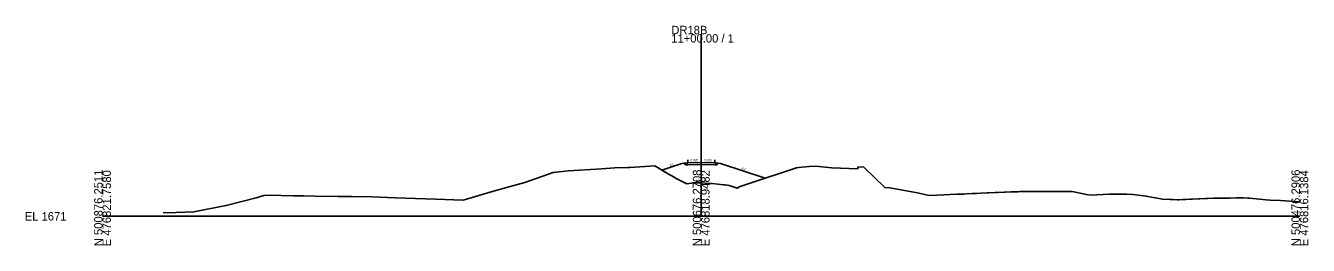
# Model space of a CAD drawing. Extents: x -26 to 403, y -10 to 2578.
# Drawn here: x -25.7 to 402.8, y 490.3 to 563.7 of the extents above; entities that cross this region are included whole.
import ezdxf

# ---------------------------------------------------------------- set-up
doc = ezdxf.new("R2010")
doc.units = 0
for name, color, linetype in [('Exist Cross Section Cell', 7, 'Continuous'), ('Exist XS Center Line Elevation Label', 7, 'Continuous'), ('Exist XS Ground Line', 7, 'Continuous'), ('Prop XS Earthwork Shape', 7, 'Continuous'), ('Prop XS EOT Tick Mark', 7, 'Continuous'), ('Prop XS Finish Grade', 7, 'Continuous'), ('Prop XS Finish Grade Earthwork', 7, 'Continuous'), ('Prop XS Finish Grade Pavement', 7, 'Continuous'), ('Prop XS Pvmt Edge Slope', 7, 'Continuous'), ('Prop XS SE Text', 7, 'Continuous'), ('Prop XS Shoulder Borrow Shape', 7, 'Continuous'), ('Prop XS Side Slope Text', 7, 'Continuous'), ('Prop XS Subgrade Earthwork', 7, 'Continuous')]:
    doc.layers.add(name, color=color, linetype=linetype)

msp = doc.modelspace()

# ---------------------------------------------------------------- linework, layer by layer
at = {"layer": 'Exist Cross Section Cell'}
for p, q in [((200, 500), (200, 560.82)), ((0, 500), (200, 500)), ((200, 500), (400, 500))]:
    msp.add_line(p, q, dxfattribs=at)
at = {"layer": 'Exist XS Ground Line'}
msp.add_lwpolyline([(20.23, 501.28), (21.67, 501.18), (30.44, 501.46), (40.61, 503.46), (41.28, 503.61), (51.27, 506.16), (53.84, 506.98), (56.42, 507.09), (59.68, 506.95), (63.72, 506.89), (67.17, 506.79), (70.98, 506.71), (78.74, 506.64), (83.24, 506.63), (89.91, 506.53), (97.84, 506.18), (107.88, 505.84), (111.23, 505.68), (120.53, 505.36), (129.88, 508.19), (136.21, 509.9), (141.11, 511.31), (150.55, 514.65), (155.67, 515.17), (166.64, 515.9), (171.16, 516.21), (175.45, 516.31), (176.16, 516.35), (184.48, 516.82), (189.01, 514.17), (189.57, 513.85), (190.15, 513.51), (191.86, 512.51), (195.19, 510.84), (196.61, 511.07), (197.17, 511.21), (197.91, 511.22), (198.83, 511.21), (199.16, 511.23), (200, 511.17), (202.69, 510.95), (203.61, 510.97), (207.44, 510.49), (208.06, 510.48), (209.3, 510.25), (210.03, 510.11), (212.01, 509.39), (213.05, 509.91), (215.39, 510.69), (231.82, 516.24), (232.6, 516.31), (233.65, 516.4), (234.93, 516.51), (236.04, 516.61), (238.17, 516.79), (243.69, 516.22), (252.36, 515.87), (252.37, 516.51), (254.34, 516.38), (261.31, 509.62), (263.07, 509.48), (272.24, 507.86), (276.04, 506.99), (278.86, 507.09), (285.42, 507.4), (285.86, 507.4), (287.1, 507.36), (287.73, 507.44), (288.64, 507.49), (290.37, 507.58), (291.14, 507.62), (292.02, 507.67), (293.58, 507.73), (295.52, 507.81), (296.1, 507.83), (298.16, 507.92), (298.63, 507.94), (299.11, 507.96), (301.17, 508.03), (301.63, 508.05), (303.59, 508.13), (305.78, 508.22), (306.42, 508.25), (307.21, 508.26), (308.63, 508.29), (311.05, 508.29), (313.85, 508.28), (316.37, 508.26), (318.83, 508.25), (320.7, 508.25), (321.08, 508.25), (322.68, 508.25), (323.28, 508.25), (323.93, 508.23), (328.71, 507.27), (330.22, 507.04), (336.32, 507.44), (339.05, 507.4), (342.13, 507.4), (344.24, 507.32), (345.32, 507.16), (346.82, 507), (348.71, 506.73), (350.99, 506.32), (351.82, 506.18), (354.09, 505.72), (356.65, 505.65), (357.56, 505.6), (359.11, 505.49), (359.69, 505.52), (360.9, 505.57), (361.87, 505.62), (363.25, 505.69), (363.64, 505.71), (364.09, 505.73), (366.14, 505.82), (366.62, 505.84), (368.64, 505.91), (369.15, 505.94), (371.13, 506.03), (371.9, 506.07), (372.34, 506.07), (373.62, 506.07), (375.5, 506.1), (376.11, 506.11), (376.73, 506.11), (378.6, 506.13), (379.58, 506.13), (381.17, 506.14), (382.65, 506.11), (383.22, 506.06), (388.77, 505.5), (390.1, 505.38), (393.57, 505.27), (399.61, 504.89), (400, 504.77)], dxfattribs=at)
at = {"layer": 'Prop XS Earthwork Shape'}
msp.add_lwpolyline([(206.5, 517.67), (221.38, 512.71), (215.39, 510.69), (213.05, 509.91), (212.01, 509.39), (210.03, 510.11), (209.3, 510.25), (208.06, 510.48), (207.44, 510.49), (203.61, 510.97), (202.69, 510.95), (200, 511.17), (199.16, 511.23), (198.83, 511.21), (197.91, 511.22), (197.17, 511.21), (196.61, 511.07), (195.19, 510.84), (191.86, 512.51), (190.15, 513.51), (189.57, 513.85), (189.01, 514.17), (186.83, 515.45), (193.5, 517.67), (194.24, 517.73), (194.82, 517.15), (195.5, 517.16), (200, 517.25), (204.5, 517.16), (205.18, 517.15), (205.76, 517.73)], close=True, dxfattribs=at)
at = {"layer": 'Prop XS EOT Tick Mark'}
for p, q in [((195.5, 517.83), (195.5, 518.83)), ((204.5, 517.83), (204.5, 518.83))]:
    msp.add_line(p, q, dxfattribs=at)
at = {"layer": 'Prop XS Finish Grade'}
for p, q in [((195.5, 517.83), (194.24, 517.73)), ((204.5, 517.83), (205.76, 517.73))]:
    msp.add_line(p, q, dxfattribs=at)
at = {"layer": 'Prop XS Finish Grade Earthwork'}
for p, q in [((193.5, 517.67), (186.83, 515.45)), ((194.24, 517.73), (193.5, 517.67)), ((205.76, 517.73), (206.5, 517.67)), ((206.5, 517.67), (221.38, 512.71))]:
    msp.add_line(p, q, dxfattribs=at)
at = {"layer": 'Prop XS Finish Grade Pavement'}
for p, q in [((195.5, 517.83), (200, 517.92)), ((200, 517.92), (204.5, 517.83))]:
    msp.add_line(p, q, dxfattribs=at)
at = {"layer": 'Prop XS Pvmt Edge Slope'}
for p, q in [((195.5, 517.83), (194.82, 517.15)), ((204.5, 517.83), (205.18, 517.15))]:
    msp.add_line(p, q, dxfattribs=at)
at = {"layer": 'Prop XS Shoulder Borrow Shape'}
for points in [[(195.5, 517.83), (194.24, 517.73), (194.82, 517.15)], [(204.5, 517.83), (205.76, 517.73), (205.18, 517.15)]]:
    msp.add_lwpolyline(points, close=True, dxfattribs=at)
at = {"layer": 'Prop XS Subgrade Earthwork'}
for p, q in [((194.82, 517.15), (194.24, 517.73)), ((195.5, 517.16), (194.82, 517.15)), ((200, 517.25), (195.5, 517.16)), ((204.5, 517.16), (200, 517.25)), ((204.5, 517.16), (205.18, 517.15)), ((205.18, 517.15), (205.76, 517.73))]:
    msp.add_line(p, q, dxfattribs=at)

# ---------------------------------------------------------------- texts
at = {"layer": 'Exist Cross Section Cell'}
for s, p in [('DR18B', (190, 560.82)), ('11+00.00 / 1', (190, 558.02)), ('EL 1671', (-26, 498.6))]:
    msp.add_text(s, height=2.8, dxfattribs=at).set_placement(p)
for s, p in [('N 500876.2511', (0, 490)), ('E 476821.7580', (2.8, 490)), ('N 500676.2708', (200, 490)), ('E 476818.9482', (202.8, 490)), ('N 500476.2906', (400, 490)), ('E 476816.1384', (402.8, 490))]:
    msp.add_text(s, height=2.8, rotation=90, dxfattribs=at).set_placement(p)
at = {"layer": 'Exist XS Center Line Elevation Label'}
msp.add_text('1682.17', height=0.75, dxfattribs=at).set_placement((198.15, 511.45))
at = {"layer": 'Prop XS SE Text'}
for rotation, p in [(1.1458, (196.44, 518.35)), (358.8542, (200.94, 518.4))]:
    msp.add_text('0.020', height=0.75, rotation=rotation, dxfattribs=at).set_placement(p)
at = {"layer": 'Prop XS Side Slope Text'}
for rotation, p in [(18.4349, (189.57, 516.64)), (341.5651, (213.42, 515.77))]:
    msp.add_text('3:1', height=0.75, rotation=rotation, dxfattribs=at).set_placement(p)

doc.saveas('drawing.dxf')
